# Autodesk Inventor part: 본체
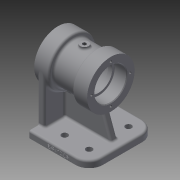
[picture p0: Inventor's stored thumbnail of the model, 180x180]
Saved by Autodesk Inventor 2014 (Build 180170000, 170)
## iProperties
Created: 2020-06
Part Number: 본체
Material: Generic
Document SubType Name: Modeling
Designer: kh
Density: 1 g/cm^3
Appearance: Default
Author: kh
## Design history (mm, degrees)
sketch "Sketch1"
  geometry: L1 (-45, 49)-(45, 49); L2 (45, 49)-(45, -49); L3 (45, -49)-(-45, -49); L4 (-45, -49)-(-45, 49); L5 (-45, 49)-(45, -49); L6 (45, 49)-(-45, -49); 1 further point
  constraints: 12 end point, 2 midpoint, 2 parallel, 1 horizontal, 1 perpendicular
  dimensions: "d0" = 90 distance of L2.end L3.end; "d1" = 98 distance of L1.end L2.end
extrude "Extrusion1" new body sketch "Sketch1" distance "d2" = 10; taper "d3" = 0 deg
sketch "Sketch3"
  geometry: L1 (-28, 80)-(50, 80); L2 (-28, 80)-(-28, 115); L3 (-28, 115)-(-6, 115); L4 (-6, 115)-(-6, 109); L5 (-6, 109)-(28, 109); L6 (28, 109)-(28, 115); L7 (28, 115)-(50, 115); L8 (50, 115)-(50, 80); L9 (-45, 0)-(45, 0) reference; L10 (45, 0)-(-45, 0) reference; L11 (-45, 0)-(45, 0) reference; 1 further point
  constraints: 16 end point, 6 perpendicular, 1 horizontal, 1 parallel
  dimensions: "d4" = 70 diameter of L3 L1; "d5" = 78 distance between parallel lines of L8 L2; "d6" = 70 diameter of L7 L1; "d7" = 58 diameter of L5 L1; "d8" = 22 distance of L2.end L3.end; "d9" = 22 distance of L6.end L7.end; "d10" = 80 distance between parallel lines of L9 L1; "d16" = 5 distance from line of L9.end L8
revolve "Revolution1" sketch "Sketch3" stored, may be unused: angle "d11" = 90 deg
sketch "Sketch4"
  geometry: L1 (45, 0)-(-45, 0) reference; L2 (45, 0)-(45, 10) reference; L3 (-45, 10)-(45, 10) reference; L4 (-45, 0)-(-45, 10) reference; L5 (-28, 45)-(-28, 115) reference; L6 (45, 10)-(45, 70.445); L7 (-11, 70.445)-(-33, 10); L8 (45, 10)-(-33, 10); L9 (45, 70.445)-(-11, 70.445); 5 further points; 2 other entities
  constraints: 8 end point, 1 parallel, 1 perpendicular, 1 point on line, 4 other
extrude "Extrusion2" join sketch "Sketch4" stored distance "d17" = 10; taper "d18" = 0 deg
sketch "Sketch5"
  geometry: L1 (0, 0)-(0, 98) reference; L2 (10, 44)-(10, 0) reference; L3 (45.359, 44)-(10, 44) reference; L4 (10, 98)-(10, 54) reference; L5 (10, 84)-(80.327, 84); L6 (10, 14)-(80, 14); L7 (10, 84)-(10, 14); C1 r 35 at (80, 49) reference; A1 r 35 centre (80, 49) between (45.359, 44) and (80, 14) reference; 3 further points
  constraints: 6 end point, 2 midpoint, 2 point on line, 2 tangent, 1 horizontal alignment, 1 parallel, 1 point on circle
  dimensions: "d21" = 70 distance between parallel lines of L6 L5 (derived)
extrude "Extrusion3" join sketch "Sketch5" distance "d22" = 10; taper "d23" = 0 deg
mirror "Mirror1"
sketch "Sketch6"
  geometry: L1 (50, 45)-(50, 115) reference; L2 (-28, 45)-(-28, 115) reference; L3 (50, 80)-(-28, 80); L4 (50, 103.5)-(32.3, 103.5); L5 (32, 103.2)-(32, 100); L6 (32, 100)-(26, 100); L7 (26, 100)-(26, 100); L8 (23, 103)-(-1, 103); L9 (-4, 100)-(-4, 100); L10 (-4, 100)-(-10, 100); L11 (-10, 100)-(-10, 103.2); L12 (-10.3, 103.5)-(-28, 103.5); L13 (-28, 103.5)-(-28, 80); L14 (50, 103.5)-(50, 80); A1 r 3 centre (23, 100) between (26, 100) and (23, 103); A2 r 3 centre (-1, 100) between (-1, 103) and (-4, 100); A3 r 0.3 centre (32.3, 103.2) between (32.3, 103.5) and (32, 103.2); A4 r 0.3 centre (-10.3, 103.2) between (-10, 103.2) and (-10.3, 103.5); 3 further points
  constraints: 24 end point, 8 parallel, 8 point on circle, 8 tangent, 6 point on line, 4 centre point, 2 equal radius, 2 midpoint, 2 perpendicular, 1 collinear
  dimensions: "d24" = 47 diameter of L4 L3; "d25" = 46 diameter of L8 L3; "d26" = 47 diameter of L12 L3; "d27" = 6 distance between parallel lines of L7 L5; "d29" = 30 distance between parallel lines of L9 L7; "d30" = 18 distance of L4.start point (32, 103.5); "d31" = 18 distance of point (-10, 103.5) L12.end; "d32" = 3 radius of A1; "d33" = 0.3 radius of A3; "d34" = 40 diameter of L6 L3; "d35" = 40 diameter of L10 L3
revolve "Revolution2" sketch "Sketch6" stored, may be unused: angle "d36" = 90 deg
sketch "Sketch7"
  geometry: C1 r 23.5 at (0, 0) reference; 2 further points
  dimensions: "d37" = 28.5 distance of point (28.5, 0) C1.centre
hole "Hole1" sketch "Sketch7" at (28.5, 0) diameter "d38" = 3.242; stored, may be unused: countersink angle "d42" = 90 deg, drill point angle "d44" = 118 deg; dims "d39" = 10, "d40" = 4, "d41" = 2, "d43" = 12
pattern_circular "Circular Pattern1" dims angle "d46" = 360 deg
workplane "Work Plane1"
mirror "Mirror2"
workplane "Work Plane2"
sketch "Sketch8"
  geometry: L1 (50, -35)-(50, 35) reference; C1 r 6 at (11, 0); 1 further point
  constraints: 1 centre point
  dimensions: "d49" = 12 diameter of C1; "d94" = 39 distance from line of L1 C1.centre
extrude "Extrusion4" join sketch "Sketch8" stored distance "d50" = 12 (= d49); taper "d51" = 0 deg
hole "Hole2" diameter "d54" = 5.188; stored, may be unused: countersink angle "d58" = 90 deg, drill point angle "d60" = 118 deg; dims "d52" = 10, "d53" = 10, "d55" = 10, "d56" = 4, "d57" = 2, "d59" = 12
fillet "Fillet1" dims "d61" = 20
sketch "Sketch9"
  geometry: L1 (-45, 49)-(-45, 35) reference; 5 further points
  constraints: 2 horizontal alignment, 1 vertical alignment
  dimensions: "d64" = 58 distance of point (-11, -29) point (-11, 29); "d65" = 36 distance of point (25, 29) point (-11, 29); "d66" = 36 distance of point (25, -29) point (-11, -29); "d67" = 70 distance from line of L1 point (25, 29); "d68" = 29 vertical distance of point (0, 0) point (-11, 29)
hole "Hole3" sketch "Sketch9" at (-11, 29), (-11, -29), (25, 29), (25, -29) diameter "d69" = 9; stored, may be unused: countersink angle "d73" = 90 deg, drill point angle "d75" = 0 deg; dims "d70" = 10, "d71" = 4, "d72" = 2, "d74" = 9
fillet "Fillet2" dims "d76" = 3
fillet "Fillet3" dims "d77" = 3
fillet "Fillet4" dims "d78" = 3
fillet "Fillet5" dims "d79" = 3
fillet "Fillet6" dims "d80" = 3
fillet "Fillet7" dims "d81" = 3
fillet "Fillet8" dims "d82" = 3
fillet "Fillet9" dims "d83" = 3
fillet "Fillet10" dims "d84" = 3
chamfer "Chamfer1" distance "d85" = 1; stored, may be unused: second distance "d86" = 2, angle "d87" = 45 deg
sketch "Sketch10"
  geometry: L1 (67, 0)-(0, 0) reference; L2 (-3, 7)-(-3, 0) reference; 2 further points
  constraints: 1 other
  dimensions: "d90" = 4 distance from line of L1 point (42, 4); "d91" = 45 distance from line of L2 point (42, 4)
emboss "Emboss1" sketch "Sketch10" dims "d0" = 90, "d1" = 98, "d92" = 0.5, "d93" = 0
body "Solid1"
node "Projected Loop1"
node "Projected Loop2"
node "Projected Loop3"
node "Projected Loop4"
other parameters: "d48" = -112
